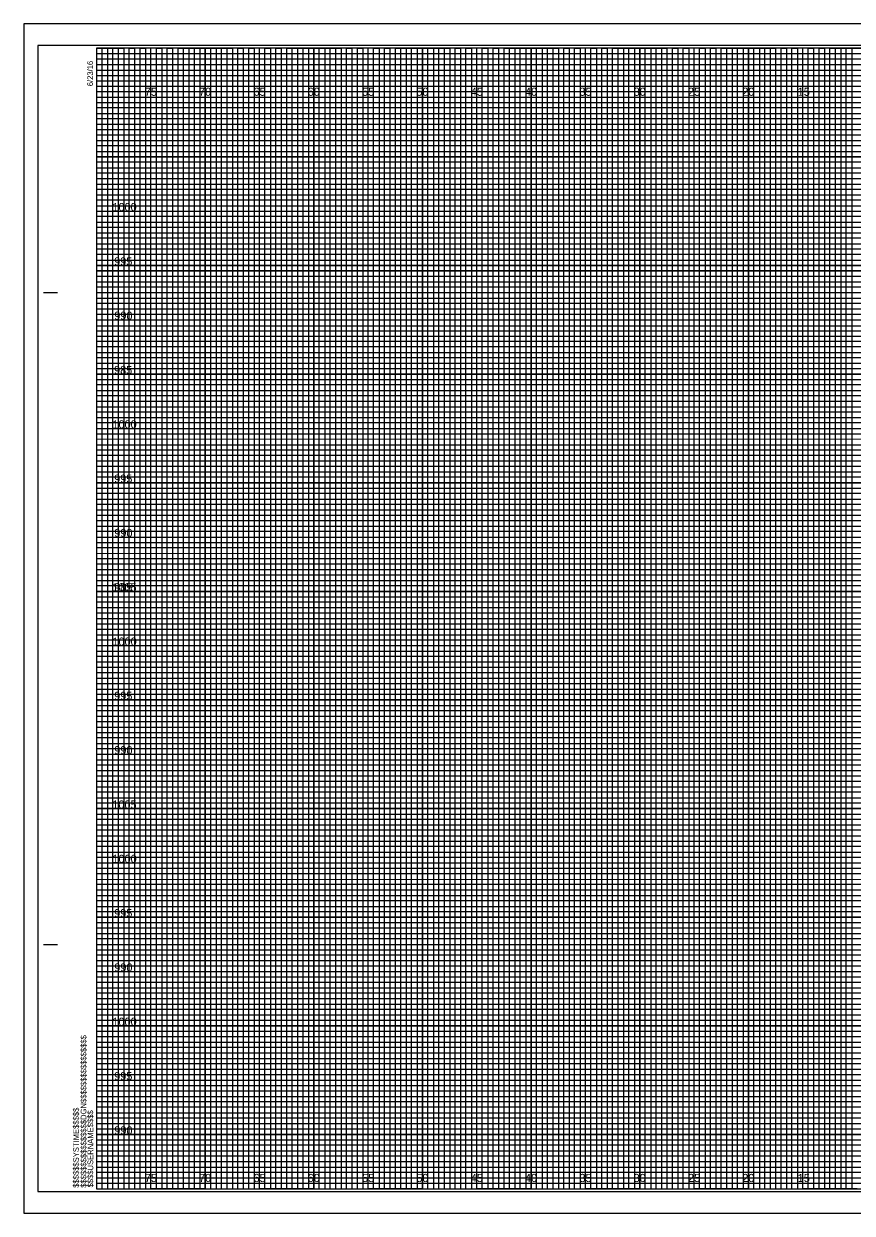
# Model space of a CAD drawing. Extents: x -7 to 162, y -2 to 107.
# Drawn here: x -6.7 to 69.5, y -2.3 to 107.3 of the extents above; entities that cross this region are included whole.
import ezdxf

# ---------------------------------------------------------------- set-up
doc = ezdxf.new("R2010")
doc.units = 0
for name, color, linetype in [('Prop XS Elevation Labels', 7, 'Continuous'), ('Prop XS Offset Labels', 7, 'Continuous'), ('Sheet Cross Section CELL', 7, 'Continuous'), ('Sheet Cross Section Grid Major CELL', 7, 'Continuous'), ('Sheet Cross Section Grid Middle CELL', 7, 'Continuous'), ('Sheet Cross Section Grid Minor 1 CELL', 7, 'Continuous'), ('Sheet Cross Section Grid Minor 2 CELL', 7, 'Continuous'), ('Sheet Cutting Line CELL', 7, 'Continuous'), ('Sheet DOT Grid CELL', 7, 'Continuous'), ('Sheet Plot Border Inside CELL', 7, 'Continuous'), ('Sheet Plot Border Outside CELL', 7, 'Continuous')]:
    doc.layers.add(name, color=color, linetype=linetype)

msp = doc.modelspace()

# ---------------------------------------------------------------- linework, layer by layer
at = {"layer": 'Sheet Cross Section CELL'}
for p, q in [((-4.9, 82.5), (-3.65, 82.5)), ((-4.85, 82.5), (-3.6, 82.5)), ((-4.9, 22.5), (-3.65, 22.5)), ((-4.85, 22.5), (-3.6, 22.5)), ((0, 0), (0, 0)), ((0, 0), (0, 0)), ((0, 0), (0, 0)), ((0, 0), (0, 0)), ((0, 0), (0, 0)), ((0, 0), (0, 0)), ((0, 0), (0, 0))]:
    msp.add_line(p, q, dxfattribs=at)
msp.add_lwpolyline([(160, 105), (0, 105), (0, 0), (160, 0)], close=True, dxfattribs=at)
at = {"layer": 'Sheet Cross Section Grid Major CELL'}
for p, q in [((5, 105), (0, 105)), ((5, 0), (5, 105)), ((15, 105), (10, 105)), ((10, 105), (10, 0)), ((15, 0), (15, 105)), ((25, 105), (20, 105)), ((20, 105), (20, 0)), ((25, 0), (25, 105)), ((35, 105), (30, 105)), ((30, 105), (30, 0)), ((35, 0), (35, 105)), ((45, 105), (40, 105)), ((40, 105), (40, 0)), ((45, 0), (45, 105)), ((55, 105), (50, 105)), ((50, 105), (50, 0)), ((55, 0), (55, 105)), ((65, 105), (60, 105)), ((60, 105), (60, 0)), ((65, 0), (65, 105)), ((10, 0), (5, 0)), ((20, 0), (15, 0)), ((30, 0), (25, 0)), ((40, 0), (35, 0)), ((50, 0), (45, 0)), ((60, 0), (55, 0)), ((70, 0), (65, 0))]:
    msp.add_line(p, q, dxfattribs=at)
for points in [[(0, 100), (160, 100), (160, 95), (0, 95)], [(0, 90), (160, 90), (160, 85), (0, 85)], [(0, 80), (160, 80), (160, 75), (0, 75)], [(0, 70), (160, 70), (160, 65), (0, 65)], [(0, 60), (160, 60), (160, 55), (0, 55)], [(0, 50), (160, 50), (160, 45), (0, 45)], [(0, 40), (160, 40), (160, 35), (0, 35)], [(0, 30), (160, 30), (160, 25), (0, 25)], [(0, 20), (160, 20), (160, 15), (0, 15)], [(0, 10), (160, 10), (160, 5), (0, 5)]]:
    msp.add_lwpolyline(points, dxfattribs=at)
at = {"layer": 'Sheet Cross Section Grid Middle CELL'}
for points in [[(0, 105), (2.5, 105), (2.5, 0), (7.5, 0), (7.5, 105), (12.5, 105), (12.5, 0), (17.5, 0), (17.5, 105), (22.5, 105), (22.5, 0), (27.5, 0), (27.5, 105), (32.5, 105), (32.5, 0), (37.5, 0), (37.5, 105), (42.5, 105), (42.5, 0), (47.5, 0), (47.5, 105), (52.5, 105), (52.5, 0), (57.5, 0), (57.5, 105), (62.5, 105), (62.5, 0), (67.5, 0), (67.5, 105), (72.5, 105)], [(0, 102.5), (137.5, 102.5)], [(0, 92.5), (160, 92.5), (160, 97.5), (0, 97.5)], [(0, 82.5), (160, 82.5), (160, 87.5), (0, 87.5)], [(0, 72.5), (160, 72.5), (160, 77.5), (0, 77.5)], [(0, 62.5), (160, 62.5), (160, 67.5), (0, 67.5)], [(0, 52.5), (160, 52.5), (160, 57.5), (0, 57.5)], [(0, 42.5), (160, 42.5), (160, 47.5), (0, 47.5)], [(0, 32.5), (160, 32.5), (160, 37.5), (0, 37.5)], [(0, 22.5), (160, 22.5), (160, 27.5), (0, 27.5)], [(0, 12.5), (160, 12.5), (160, 17.5), (0, 17.5)], [(0, 2.5), (160, 2.5), (160, 7.5), (0, 7.5)]]:
    msp.add_lwpolyline(points, dxfattribs=at)
at = {"layer": 'Sheet Cross Section Grid Minor 1 CELL'}
for p, q in [((0, 104.5), (130, 104.5)), ((130, 103.99), (0, 103.99)), ((0, 103.99), (0, 103.5)), ((0, 103.5), (130, 103.5)), ((130, 102.95), (0, 102.95)), ((0, 102.95), (0, 102)), ((0, 102), (160, 102))]:
    msp.add_line(p, q, dxfattribs=at)
for points in [[(0, 101.5), (135, 101.5), (160, 101.5), (160, 101), (0, 101)], [(0, 100.5), (160, 100.5), (160, 99.5), (0, 99.5)], [(0, 99), (160, 99), (160, 98.5), (0, 98.49)], [(0, 98), (160, 98), (160, 97), (0, 97)], [(0, 96.5), (160, 96.5), (160, 96), (0, 96)], [(0, 95.5), (160, 95.5), (160, 94.5), (0, 94.5)], [(0, 94), (160, 94), (160, 93.5), (0, 93.5)], [(0, 93), (160, 93), (160, 92), (0, 92)], [(0, 91.5), (160, 91.5), (160, 91), (0, 91)], [(0, 90.5), (160, 90.5), (160, 89.5), (0, 89.5)], [(0, 89), (160, 89), (160, 88.5), (0, 88.5)], [(0, 88), (160, 88), (160, 86.98), (160, 86.5), (160, 86), (0, 86)], [(0, 87), (160, 87), (160, 86.5), (0, 86.5)], [(0, 85.5), (160, 85.5), (160, 84.5), (0, 84.52)], [(0, 84.52), (160, 84.5), (160, 84), (0, 84)], [(0, 83.5), (160, 83.5), (160, 83), (0, 83)], [(0, 82), (160, 82), (160, 81.5), (0, 81.5)], [(0, 81), (160, 81), (160, 80.5), (0, 80.5)], [(-0.04, 79.45), (160, 79.45), (160, 78.94), (-0.04, 78.94)], [(0, 78.5), (160, 78.5), (160, 78), (0, 78)], [(0, 77), (160, 77), (160, 76.5), (0, 76.5)], [(0, 76), (160, 76), (160, 75.5), (0, 75.5)], [(0, 74.5), (160, 74.5), (160, 74), (0, 74)], [(0, 73.5), (160, 73.5), (160, 73), (0, 73)], [(0, 72), (160, 72), (160, 71.5), (0, 71.5)], [(0, 71), (160, 71), (160, 70.5), (0, 70.5)], [(0, 69.5), (160, 69.5), (160, 68.99), (0, 69)], [(0, 68.5), (160, 68.5), (160, 68), (0, 68)], [(0, 67), (160, 67), (160, 66.5), (0, 66.5)], [(0, 66), (160, 66), (160, 65.5), (0, 65.5)], [(0, 64.5), (160, 64.5), (160, 64), (0, 64)], [(0, 63.5), (160, 63.5), (160, 63), (0, 63)], [(0, 62), (160, 62), (160, 61.5), (0, 61.5)], [(0, 61), (160, 61), (160, 60.5), (0, 60.5)], [(0, 59.5), (160, 59.5), (160, 59), (0, 59)], [(0, 58.5), (160.03, 58.45), (160, 58), (0, 58)], [(0, 57), (160, 57), (160, 56.5), (0, 56.5)], [(0, 56), (160, 56), (160, 55.5), (0, 55.5)], [(0, 54.5), (160, 54.5), (160, 54), (0, 54)], [(0, 53.5), (160, 53.5), (160, 53), (0, 53)], [(0, 52), (160, 52), (160, 51.5), (0, 51.5)], [(0, 51), (160, 51), (160, 50.5), (0, 50.5)], [(0, 49.5), (160, 49.5), (160, 49), (0, 49)], [(0, 48.5), (160, 48.5), (160, 48), (0, 48)], [(0, 47), (160, 47), (160, 46.5), (0, 46.5)], [(0, 46), (160, 46), (160, 45.5), (0, 45.5)], [(0, 44.5), (160, 44.5), (160, 44), (0, 44)], [(0, 43.5), (160, 43.5), (160, 43), (0, 43)], [(0, 42), (160, 42), (160, 41.5), (0, 41.5)], [(0, 41), (160, 41), (160, 40.5), (0, 40.5)], [(0, 39.5), (160, 39.5), (160, 38.99), (0, 39)], [(0, 38.5), (160, 38.5), (160, 38), (0, 38)], [(0, 37), (160, 37), (160, 36.5), (0, 36.5)], [(0, 36), (160, 36), (160, 35.5), (0, 35.5)], [(0, 34.5), (160, 34.5), (160, 34), (0, 34)], [(0, 33.5), (160, 33.5), (160, 33), (0, 33)], [(0, 32), (160, 32), (160, 31.5), (0, 31.5)], [(0, 31), (160, 31), (160, 30.5), (0, 30.5)], [(0, 29.5), (160, 29.5), (160, 29), (0, 29)], [(0, 28.5), (160.03, 28.46), (160, 28), (0, 28)], [(0, 27), (160, 27), (160, 26.5), (0, 26.5)], [(0, 26), (160, 26), (160, 25.5), (0, 25.5)], [(0, 24.5), (160, 24.5), (160, 24), (0, 24)], [(0, 23.5), (160, 23.5), (160, 23), (0, 23)], [(0, 22), (160, 22), (160, 21.5), (0, 21.5)], [(0, 21), (160, 21), (160, 20.5), (0, 20.5)], [(0, 19.5), (160, 19.5), (160, 19), (0, 19)], [(0, 18.5), (160, 18.5), (160, 18), (0, 18)], [(0, 17), (160, 17), (160, 16.5), (0, 16.5)], [(0, 16), (160, 16), (160, 15.5), (0, 15.5)], [(0, 14.5), (160, 14.5), (160, 14), (0, 14)], [(0, 13.5), (160, 13.5), (160, 13), (0, 13)], [(0, 12), (160, 12), (160, 11.5), (0, 11.5)], [(0, 11), (160, 11), (160, 10.5), (0, 10.5)], [(0, 9.5), (160, 9.5), (160, 9), (0, 9)], [(0, 8.5), (160, 8.5), (160, 8), (0, 8)], [(0, 7), (160, 7), (160, 6.5), (0, 6.5)], [(0, 6), (160, 6), (160, 5.5), (0, 5.5)], [(0, 4.5), (160, 4.5), (160, 4), (0, 4)], [(0, 3.5), (160, 3.5), (160, 3), (0, 3)], [(0, 2), (160, 2), (160, 1.5), (0, 1.5)], [(0, 1), (160, 1), (160, 0.5), (0, 0.5)]]:
    msp.add_lwpolyline(points, dxfattribs=at)
at = {"layer": 'Sheet Cross Section Grid Minor 2 CELL'}
for points in [[(0, 0), (0.5, 0), (0.5, 105), (1, 105), (1, 0)], [(1, 0), (1.5, 0), (1.5, 105), (2, 105), (2, 0)], [(2.5, 0), (3, 0), (3, 105), (3.5, 105), (3.5, 0)], [(3.5, 0), (4, 0), (4, 105), (4.5, 105), (4.5, 0)], [(5, 0), (5.5, 0), (5.5, 105), (6, 105), (6, 0)], [(6, 0), (6.5, 0), (6.5, 105), (7, 105), (7, 0)], [(7.5, 0), (8, 0), (8, 105), (8.5, 105), (8.5, 0)], [(8.5, 0), (9, 0), (9, 105), (9.5, 105), (9.5, 0)], [(10, 0), (10.5, 0), (10.5, 105), (11, 105), (11, 0)], [(11, 0), (11.5, 0), (11.5, 105), (12, 105), (12, 0)], [(12.5, 0), (13, 0), (13, 105), (13.5, 105), (13.5, 0)], [(13.5, 0), (14, 0), (14, 105), (14.5, 105), (14.5, 0)], [(15, 0), (15.5, 0), (15.5, 105), (16, 105), (16, 0)], [(16, 0), (16.5, 0), (16.5, 105), (17, 105), (17, 0)], [(17.5, 0), (18, 0), (18, 105), (18.5, 105), (18.5, 0)], [(18.5, 0), (19, 0), (19, 105), (19.5, 105), (19.5, 0)], [(20, 0), (20.5, 0), (20.5, 105), (21, 105), (21, 0)], [(21, 0), (21.5, 0), (21.5, 105), (22, 105), (22, 0)], [(22.5, 0), (23, 0), (23, 105), (23.5, 105), (23.5, 0)], [(23.5, 0), (24, 0), (24, 105), (24.5, 105), (24.5, 0)], [(25, 0), (25.5, 0), (25.5, 105), (26, 105), (26, 0)], [(26, 0), (26.5, 0), (26.5, 105), (27, 105), (27, 0)], [(27.5, 0), (28, 0), (28, 105), (28.5, 105), (28.5, 0)], [(28.5, 0), (29, 0), (29, 105), (29.5, 105), (29.5, 0)], [(30, 0), (30.5, 0), (30.5, 105), (31, 105), (31, 0)], [(31, 0), (31.5, 0), (31.5, 105), (32, 105), (32, 0)], [(32.5, 0), (33, 0), (33, 105), (33.5, 105), (33.5, 0)], [(33.5, 0), (34, 0), (34, 105), (34.5, 105), (34.5, 0)], [(35, 0), (35.5, 0), (35.5, 105), (36, 105), (36, 0)], [(36, 0), (36.5, 0), (36.5, 105), (37, 105), (37, 0)], [(37.5, 0), (38, 0), (38, 105), (38.5, 105), (38.5, 0)], [(38.5, 0), (39, 0), (39, 105), (39.5, 105), (39.5, 0)], [(40, 0), (40.5, 0), (40.5, 105), (41, 105), (41, 0)], [(41, 0), (41.5, 0), (41.5, 105), (42, 105), (42, 0)], [(42.5, 0), (43, 0), (43, 105), (43.5, 105), (43.5, 0)], [(43.5, 0), (44, 0), (44, 105), (44.5, 105), (44.5, 0)], [(45, 0), (45.5, 0), (45.5, 105), (46, 105), (46, 0)], [(46, 0), (46.5, 0), (46.5, 105), (47, 105), (47, 0)], [(47.5, 0), (48, 0), (48, 105), (48.5, 105), (48.5, 0)], [(48.5, 0), (49, 0), (49, 105), (49.5, 105), (49.5, 0)], [(50, 0), (50.5, 0), (50.5, 105), (51, 105), (51, 0)], [(51, 0), (51.5, 0), (51.5, 105), (52, 105), (52, 0)], [(52.5, 0), (53, 0), (53, 105), (53.5, 105), (53.5, 0)], [(53.5, 0), (54, 0), (54, 105), (54.5, 105), (54.5, 0)], [(55, 0), (55.5, 0), (55.5, 105), (56, 105), (56, 0)], [(56, 0), (56.5, 0), (56.5, 105), (57, 105), (57, 0)], [(57.5, 0), (58, 0), (58, 105), (58.5, 105), (58.5, 0)], [(58.5, 0), (59, 0), (59, 105), (59.5, 105), (59.5, 0)], [(60, 0), (60.5, 0), (60.5, 105), (61, 105), (61, 0)], [(61, 0), (61.5, 0), (61.5, 105), (62, 105), (62, 0)], [(62.5, 0), (63, 0), (63, 105), (63.5, 105), (63.5, 0)], [(63.5, 0), (64, 0), (64, 105), (64.5, 105), (64.5, 0)], [(65, 0), (65.5, 0), (65.5, 105), (66, 105), (66, 0)], [(66, 0), (66.5, 0), (66.5, 105), (67, 105), (67, 0)], [(67.5, 0), (68, 0), (68, 105), (68.5, 105), (68.5, 0)], [(68.5, 0), (69, 0), (69, 105), (69.5, 105), (69.5, 0)]]:
    msp.add_lwpolyline(points, dxfattribs=at)
at = {"layer": 'Sheet Cutting Line CELL'}
for p, q in [((161.65, 107.25), (-6.7, 107.25)), ((-6.7, 107.25), (-6.7, -2.25)), ((-6.7, -2.25), (161.65, -2.25))]:
    msp.add_line(p, q, dxfattribs=at)
at = {"layer": 'Sheet DOT Grid CELL'}
for p, q in [((5, 0), (5, 105)), ((10, 0), (10, 105)), ((15, 0), (15, 105)), ((20, 0), (20, 105)), ((25, 0), (25, 105)), ((30, 0), (30, 105)), ((35, 0), (35, 105)), ((40, 0), (40, 105)), ((45, 0), (45, 105)), ((50, 0), (50, 105)), ((55, 0), (55, 105)), ((60, 0), (60, 105)), ((65, 0), (65, 105)), ((0, 100), (160, 100)), ((0, 95), (160, 95)), ((0, 90), (160, 90)), ((0, 85), (160, 85)), ((0, 80), (160, 80)), ((0, 75), (160, 75)), ((0, 70), (160, 70)), ((0, 65), (160, 65)), ((0, 60), (160, 60)), ((0, 55), (160, 55)), ((0, 50), (160, 50)), ((0, 45), (160, 45)), ((0, 40), (160, 40)), ((0, 35), (160, 35)), ((0, 30), (160, 30)), ((0, 25), (160, 25)), ((0, 20), (160, 20)), ((0, 15), (160, 15)), ((0, 10), (160, 10)), ((0, 5), (160, 5))]:
    msp.add_line(p, q, dxfattribs=at)
at = {"layer": 'Sheet Plot Border Inside CELL'}
msp.add_lwpolyline([(-5.4, -0.25), (161.2, -0.25), (161.2, 105.25), (-5.4, 105.25)], close=True, dxfattribs=at)
at = {"layer": 'Sheet Plot Border Outside CELL'}
msp.add_lwpolyline([(-6.7, -2.25), (161.65, -2.25), (161.65, 107.25), (-6.7, 107.25)], close=True, dxfattribs=at)

# ---------------------------------------------------------------- texts
at = {"layer": 'Prop XS Elevation Labels'}
for s, p in [('1000', (1.46, 90)), ('995', (1.62, 85)), ('990', (1.63, 80)), ('985', (1.61, 75)), ('1000', (1.46, 70)), ('995', (1.62, 65)), ('990', (1.63, 60)), ('1005', (1.45, 55)), ('985', (1.61, 55)), ('1000', (1.46, 50)), ('995', (1.62, 45)), ('990', (1.63, 40)), ('1005', (1.45, 35)), ('1000', (1.46, 30)), ('995', (1.62, 25)), ('990', (1.63, 20)), ('1000', (1.46, 15)), ('995', (1.62, 10)), ('990', (1.63, 5))]:
    msp.add_text(s, height=0.75, dxfattribs=at).set_placement(p)
at = {"layer": 'Prop XS Offset Labels'}
for s, p in [('75', (4.44, 100.62)), ('70', (9.43, 100.62)), ('65', (14.44, 100.62)), ('60', (19.43, 100.62)), ('55', (24.44, 100.62)), ('50', (29.43, 100.62)), ('45', (34.44, 100.62)), ('40', (39.43, 100.62)), ('35', (44.44, 100.62)), ('30', (49.43, 100.62)), ('25', (54.44, 100.62)), ('20', (59.43, 100.62)), ('15', (64.53, 100.62)), ('75', (4.44, 0.62)), ('70', (9.43, 0.62)), ('65', (14.44, 0.62)), ('60', (19.43, 0.62)), ('55', (24.44, 0.62)), ('50', (29.43, 0.62)), ('45', (34.44, 0.62)), ('40', (39.43, 0.62)), ('35', (44.44, 0.62)), ('30', (49.43, 0.62)), ('25', (54.44, 0.62)), ('20', (59.43, 0.62)), ('15', (64.53, 0.62))]:
    msp.add_text(s, height=0.75, dxfattribs=at).set_placement(p)
at = {"layer": 'Sheet Cross Section CELL'}
for s, p in [('6/23/16', (-0.33, 101.5)), ('$$$$$$$$$$$$$$$$DGN$$$$$$$$$$$$$$$$', (-0.94, 0.09)), ('$$$$$$SYSTIME$$$$$', (-1.63, 0.09)), ('$$$$USERNAME$$$$', (-0.31, 0.12))]:
    msp.add_text(s, height=0.525, rotation=90, dxfattribs=at).set_placement(p)

doc.saveas('drawing.dxf')
